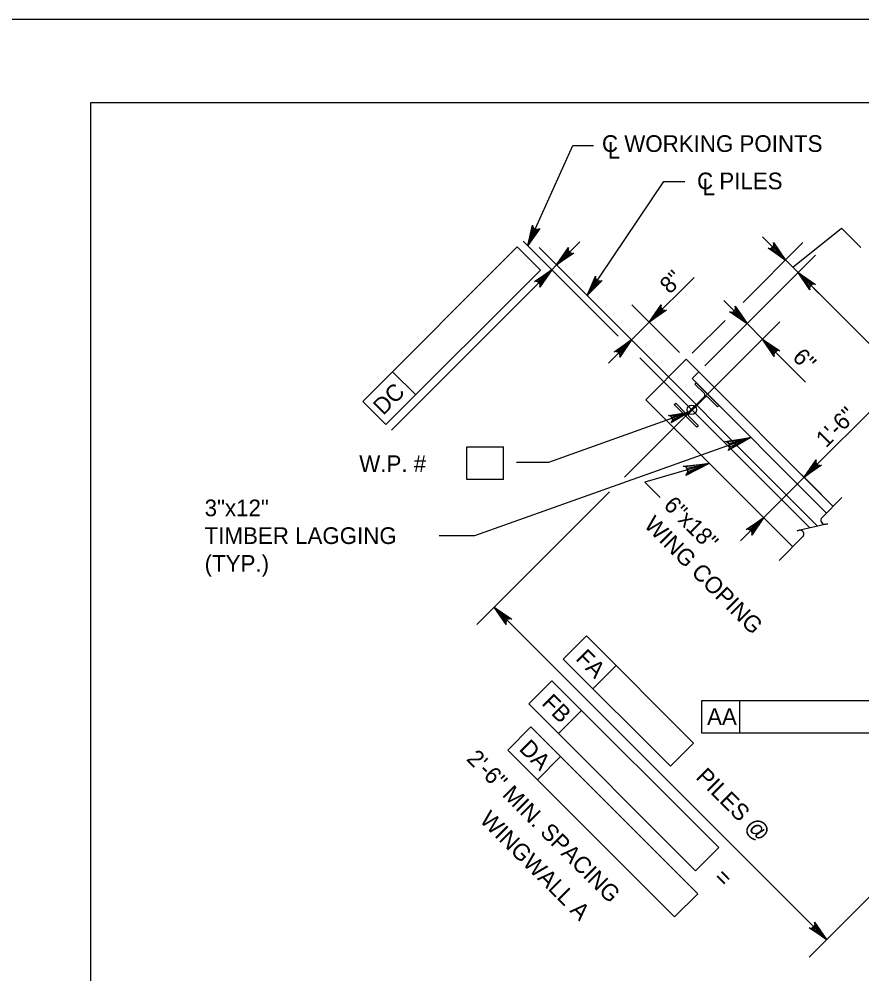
# Model space of a CAD drawing. Extents: x 638304 to 640306, y 296653 to 298435.
# Drawn here: x 639303.6 to 639455.2, y 298263.7 to 298435.5 of the extents above; entities that cross this region are included whole.
import ezdxf

# ---------------------------------------------------------------- set-up
doc = ezdxf.new("R2010")
doc.units = 0
for name, color, linetype in [('2', 7, 'Continuous'), ('3', 7, 'Continuous'), ('Level 2', 7, 'Continuous'), ('Level 3', 7, 'Continuous'), ('Level 4', 7, 'Continuous'), ('Level 5', 7, 'Continuous'), ('Level 52', 7, 'Continuous'), ('Level 8', 7, 'Continuous'), ('PLT-BNDY', 7, 'Continuous')]:
    doc.layers.add(name, color=color, linetype=linetype)

# ---------------------------------------------------------------- blocks, each defined once
blk = doc.blocks.new('HPILE')
at = {"layer": '3'}
for p, q in [((-0.12, -2.66), (-0.12, 2.66)), ((0.12, 2.66), (0.12, -2.66)), ((-3.67, -3.1), (-0.56, -3.1))]:
    blk.add_line(p, q, dxfattribs=at)
for points in [[(-0.56, 3.1), (-3.67, 3.1), (-3.67, 3.54), (3.67, 3.54), (3.67, 3.1), (0.56, 3.1)], [(0.56, -3.1), (3.67, -3.1), (3.67, -3.54), (-3.67, -3.54), (-3.67, -3.1)]]:
    blk.add_lwpolyline(points, dxfattribs=at)
for centre, start, end in [((-0.56, 2.66), 0, 90), ((0.56, 2.66), 90, 180), ((-0.56, -2.66), 270, 0), ((0.56, -2.66), 180, 270)]:
    blk.add_arc(centre, 0.438, start, end, dxfattribs=at)

msp = doc.modelspace()

# ---------------------------------------------------------------- linework, layer by layer
at = {"layer": '2'}
for p, q in [((639316.46, 297856.46), (639316.46, 298420.46)), ((639316.46, 298420.46), (640102.46, 298420.46))]:
    msp.add_line(p, q, dxfattribs=at)
at = {"layer": 'Level 2'}
for p, q in [((639423.59, 298374.28), (639416.29, 298366.99)), ((639450.03, 298347.83), (639423.59, 298374.28)), ((639442.74, 298340.54), (639416.29, 298366.99))]:
    msp.add_line(p, q, dxfattribs=at)
at = {"layer": 'Level 3'}
for p in [(639425.85, 298372.02), (639448.82, 298346.62)]:
    msp.add_line(p, (639424.63, 298370.81), dxfattribs=at)
at = {"layer": 'Level 4'}
for p, q in [((639403.15, 298412.72), (639406.91, 298412.72)), ((639419.56, 298406.24), (639423.31, 298406.24)), ((639442.75, 298390.82), (639451.5, 298397.87)), ((639451.5, 298397.87), (639455, 298394.38)), ((639443.7, 298389.87), (639437.27, 298396.3)), ((639365.41, 298366.69), (639393.19, 298394.48)), ((639393.19, 298394.48), (639397.36, 298390.31)), ((639411.32, 298378.45), (639394.24, 298395.52)), ((639413.54, 298377.97), (639397.13, 298394.38)), ((639400.26, 298391.25), (639404.42, 298395.42)), ((639433.79, 298384.49), (639444.56, 298395.26)), ((639441.44, 298392.13), (639438.83, 298394.73)), ((639426.93, 298373.11), (639446.82, 298393)), ((639400.26, 298391.25), (639399.39, 298390.38)), ((639369.57, 298362.52), (639397.36, 298390.31)), ((639399.39, 298390.38), (639370.55, 298361.55)), ((639416.92, 298380.95), (639424.98, 298389)), ((639502.92, 298330.64), (639443.7, 298389.87)), ((639446.47, 298387.09), (639448.56, 298385.01)), ((639447.22, 298344.29), (639407.29, 298384.21)), ((639422.39, 298375.48), (639413.8, 298384.07)), ((639426.93, 298373.11), (639437.63, 298383.81)), ((639434.51, 298380.69), (639430.34, 298384.85)), ((639440.41, 298381.03), (639412.47, 298353.09)), ((639413.74, 298377.76), (639416.92, 298380.95)), ((639424.67, 298375.37), (639430.57, 298381.26)), ((639434.51, 298380.69), (639437.29, 298377.91)), ((639413.74, 298377.76), (639409.58, 298373.6)), ((639437.29, 298377.91), (639445.02, 298370.18)), ((639445.8, 298343.97), (639415.26, 298374.51)), ((639370.74, 298372.03), (639374.91, 298367.86)), ((639444.8, 298353.07), (639460.41, 298368.69)), ((639365.41, 298366.69), (639369.57, 298362.52)), ((639384.1, 298358.56), (639390.68, 298358.56)), ((639384.1, 298352.66), (639384.1, 298358.56)), ((639390.68, 298352.66), (639390.68, 298358.56)), ((639437.5, 298345.78), (639444.8, 298353.07)), ((639444.36, 298353.51), (639447.92, 298349.95)), ((639390.68, 298352.66), (639384.1, 298352.66)), ((639409.8, 298350.42), (639385.93, 298326.55)), ((639437.06, 298346.22), (639440.63, 298342.65)), ((639437.5, 298345.78), (639433.34, 298341.61)), ((639448.82, 298269.91), (639389.05, 298329.67)), ((639405.64, 298324.52), (639401.47, 298320.35)), ((639405.64, 298324.52), (639424.89, 298305.26)), ((639401.47, 298320.35), (639420.73, 298301.09)), ((639410.97, 298319.18), (639406.8, 298315.02)), ((639399.41, 298316.47), (639395.24, 298312.31)), ((639399.41, 298316.47), (639429.42, 298286.46)), ((639395.24, 298312.31), (639425.25, 298282.3)), ((639426.36, 298312.93), (639461.6, 298312.93)), ((639426.36, 298307.03), (639426.36, 298312.93)), ((639433.2, 298307.03), (639433.2, 298312.93)), ((639404.75, 298311.14), (639400.58, 298306.97)), ((639395.64, 298308.15), (639391.47, 298303.98)), ((639395.64, 298308.15), (639425.65, 298278.14)), ((639461.6, 298307.03), (639426.36, 298307.03)), ((639424.89, 298305.26), (639420.73, 298301.09)), ((639391.47, 298303.98), (639421.48, 298273.98)), ((639400.98, 298302.82), (639396.81, 298298.65)), ((639473.45, 298294.53), (639445.7, 298266.78)), ((639429.42, 298286.46), (639425.25, 298282.3)), ((639425.65, 298278.14), (639421.48, 298273.98))]:
    msp.add_line(p, q, dxfattribs=at)
for points in [[(639395.06, 298394.71), (639403.15, 298412.72)], [(639405.77, 298385.73), (639419.56, 298406.24)], [(639395.06, 298394.71), (639395.94, 298398.39), (639396.01, 298398.05), (639396.17, 298397.81), (639396.38, 298397.67), (639396.63, 298397.61), (639396.92, 298397.64), (639397.22, 298397.82), (639395.06, 298394.71), (639396.92, 298397.64), (639396.63, 298397.61), (639395.06, 298394.71), (639396.38, 298397.67), (639396.17, 298397.81), (639395.06, 298394.71), (639396.01, 298398.05)], [(639400.26, 298391.25), (639402.4, 298394.38), (639402.33, 298394.03), (639402.41, 298393.75), (639402.55, 298393.54), (639402.76, 298393.4), (639403.04, 298393.33), (639403.38, 298393.39), (639400.26, 298391.25), (639403.04, 298393.33), (639402.76, 298393.4), (639400.26, 298391.25), (639402.55, 298393.54), (639402.41, 298393.75), (639400.26, 298391.25), (639402.33, 298394.03)], [(639441.44, 298392.13), (639438.31, 298394.27), (639438.66, 298394.21), (639438.94, 298394.28), (639439.14, 298394.42), (639439.29, 298394.63), (639439.36, 298394.91), (639439.3, 298395.25), (639441.44, 298392.13), (639439.36, 298394.91), (639439.29, 298394.63), (639441.44, 298392.13), (639439.14, 298394.42), (639438.94, 298394.28), (639441.44, 298392.13), (639438.66, 298394.21)], [(639399.39, 298390.38), (639397.25, 298387.25), (639397.31, 298387.6), (639397.24, 298387.88), (639397.09, 298388.09), (639396.89, 298388.23), (639396.6, 298388.3), (639396.26, 298388.24), (639399.39, 298390.38), (639396.6, 298388.3), (639396.89, 298388.23), (639399.39, 298390.38), (639397.09, 298388.09), (639397.24, 298387.88), (639399.39, 298390.38), (639397.31, 298387.6)], [(639405.77, 298385.73), (639407.27, 298389.21), (639407.28, 298388.86), (639407.4, 298388.6), (639407.59, 298388.42), (639407.82, 298388.32), (639408.11, 298388.3), (639408.43, 298388.43), (639405.77, 298385.73), (639408.11, 298388.3), (639407.82, 298388.32), (639405.77, 298385.73), (639407.59, 298388.42), (639407.4, 298388.6), (639405.77, 298385.73), (639407.28, 298388.86)], [(639443.7, 298389.87), (639446.82, 298387.74), (639446.48, 298387.8), (639446.2, 298387.72), (639445.99, 298387.58), (639445.84, 298387.37), (639445.77, 298387.09), (639445.83, 298386.75), (639443.7, 298389.87), (639445.77, 298387.09), (639445.84, 298387.37), (639443.7, 298389.87), (639445.99, 298387.58), (639446.2, 298387.72), (639443.7, 298389.87), (639446.48, 298387.8)], [(639416.92, 298380.95), (639419.06, 298384.07), (639419, 298383.73), (639419.07, 298383.45), (639419.22, 298383.24), (639419.42, 298383.09), (639419.71, 298383.02), (639420.05, 298383.08), (639416.92, 298380.95), (639419.71, 298383.02), (639419.42, 298383.09), (639416.92, 298380.95), (639419.22, 298383.24), (639419.07, 298383.45), (639416.92, 298380.95), (639419, 298383.73)], [(639434.51, 298380.69), (639431.38, 298382.82), (639431.73, 298382.76), (639432.01, 298382.83), (639432.22, 298382.98), (639432.36, 298383.19), (639432.43, 298383.47), (639432.37, 298383.81), (639434.51, 298380.69), (639432.43, 298383.47), (639432.36, 298383.19), (639434.51, 298380.69), (639432.22, 298382.98), (639432.01, 298382.83), (639434.51, 298380.69), (639431.73, 298382.76)], [(639413.74, 298377.76), (639411.61, 298374.64), (639411.67, 298374.98), (639411.59, 298375.27), (639411.45, 298375.47), (639411.24, 298375.62), (639410.96, 298375.69), (639410.62, 298375.63), (639413.74, 298377.76), (639410.96, 298375.69), (639411.24, 298375.62), (639413.74, 298377.76), (639411.45, 298375.47), (639411.59, 298375.27), (639413.74, 298377.76), (639411.67, 298374.98)], [(639437.29, 298377.91), (639440.41, 298375.77), (639440.07, 298375.83), (639439.79, 298375.76), (639439.58, 298375.61), (639439.44, 298375.41), (639439.36, 298375.13), (639439.42, 298374.78), (639437.29, 298377.91), (639439.36, 298375.13), (639439.44, 298375.41), (639437.29, 298377.91), (639439.58, 298375.61), (639439.79, 298375.76), (639437.29, 298377.91), (639440.07, 298375.83)], [(639424.13, 298364.75), (639398.83, 298355.74), (639393.04, 298355.74)], [(639424.13, 298364.75), (639420.86, 298362.84), (639421.06, 298363.13), (639421.12, 298363.41), (639421.07, 298363.66), (639420.95, 298363.88), (639420.73, 298364.07), (639420.39, 298364.16), (639424.13, 298364.75), (639420.73, 298364.07), (639420.95, 298363.88), (639424.13, 298364.75), (639421.07, 298363.66), (639421.12, 298363.41), (639424.13, 298364.75), (639421.06, 298363.13)], [(639435.21, 298360.23), (639385.48, 298342.55), (639379.16, 298342.55)], [(639444.8, 298353.07), (639446.94, 298356.2), (639446.87, 298355.85), (639446.95, 298355.57), (639447.09, 298355.37), (639447.3, 298355.22), (639447.58, 298355.15), (639447.92, 298355.21), (639444.8, 298353.07), (639447.58, 298355.15), (639447.3, 298355.22), (639444.8, 298353.07), (639447.09, 298355.37), (639446.95, 298355.57), (639444.8, 298353.07), (639446.87, 298355.85)], [(639427.72, 298355.52), (639416.12, 298352.18), (639418.9, 298349.41)], [(639437.5, 298345.78), (639435.37, 298342.65), (639435.43, 298343), (639435.36, 298343.28), (639435.21, 298343.48), (639435, 298343.63), (639434.72, 298343.7), (639434.38, 298343.64), (639437.5, 298345.78), (639434.72, 298343.7), (639435, 298343.63), (639437.5, 298345.78), (639435.21, 298343.48), (639435.36, 298343.28), (639437.5, 298345.78), (639435.43, 298343)], [(639389.05, 298329.67), (639392.18, 298327.54), (639391.84, 298327.6), (639391.55, 298327.53), (639391.35, 298327.38), (639391.2, 298327.17), (639391.13, 298326.89), (639391.19, 298326.55), (639389.05, 298329.67), (639391.13, 298326.89), (639391.2, 298327.17), (639389.05, 298329.67), (639391.35, 298327.38), (639391.55, 298327.53), (639389.05, 298329.67), (639391.84, 298327.6)], [(639448.82, 298269.91), (639445.7, 298272.04), (639446.04, 298271.98), (639446.32, 298272.05), (639446.53, 298272.2), (639446.67, 298272.41), (639446.75, 298272.69), (639446.68, 298273.03), (639448.82, 298269.91), (639446.75, 298272.69), (639446.67, 298272.41), (639448.82, 298269.91), (639446.53, 298272.2), (639446.32, 298272.05), (639448.82, 298269.91), (639446.04, 298271.98)]]:
    msp.add_lwpolyline(points, dxfattribs=at)
for points in [[(639395.06, 298394.71), (639396.49, 298397.3), (639396.04, 298397.5)], [(639439.7, 298394.56), (639439.01, 298393.87), (639441.44, 298392.13)], [(639401.99, 298393.68), (639402.69, 298392.99), (639400.26, 298391.25)], [(639396.96, 298388.64), (639397.65, 298387.95), (639399.39, 298390.38)], [(639446.13, 298388.14), (639445.43, 298387.44), (639443.7, 298389.87)], [(639405.77, 298385.73), (639407.62, 298388.04), (639407.22, 298388.32)], [(639418.66, 298383.38), (639419.35, 298382.68), (639416.92, 298380.95)], [(639432.77, 298383.12), (639432.08, 298382.42), (639434.51, 298380.69)], [(639411.31, 298376.03), (639412.01, 298375.33), (639413.74, 298377.76)], [(639439.72, 298376.17), (639439.02, 298375.48), (639437.29, 298377.91)], [(639424.13, 298364.75), (639421.27, 298363.99), (639421.43, 298363.53)], [(639435.21, 298360.23), (639432.35, 298359.47), (639432.52, 298359.01)], [(639446.53, 298355.5), (639447.23, 298354.81), (639444.8, 298353.07)], [(639435.07, 298344.04), (639435.77, 298343.35), (639437.5, 298345.78)], [(639391.49, 298327.94), (639390.79, 298327.24), (639389.05, 298329.67)], [(639447.09, 298272.34), (639446.39, 298271.64), (639448.82, 298269.91)]]:
    msp.add_lwpolyline(points, close=True, dxfattribs=at)
msp.add_circle((639424.57, 298365.19), 0.849, dxfattribs=at)
at = {"layer": 'Level 52'}
for points in [[(639435.21, 298360.23), (639431.12, 298357.85), (639431.37, 298358.2), (639431.44, 298358.56), (639431.39, 298358.87), (639431.23, 298359.15), (639430.96, 298359.38), (639430.54, 298359.49), (639435.21, 298360.23), (639430.96, 298359.38), (639431.23, 298359.15), (639435.21, 298360.23), (639431.39, 298358.87), (639431.44, 298358.56), (639435.21, 298360.23), (639431.37, 298358.2)], [(639427.72, 298355.52), (639423.49, 298353.39), (639423.77, 298353.73), (639423.86, 298354.08), (639423.83, 298354.4), (639423.69, 298354.68), (639423.42, 298354.93), (639423.01, 298355.07), (639427.72, 298355.52), (639423.42, 298354.93), (639423.69, 298354.68), (639427.72, 298355.52), (639423.83, 298354.4), (639423.86, 298354.08), (639427.72, 298355.52), (639423.77, 298353.73)]]:
    msp.add_lwpolyline(points, dxfattribs=at)
at = {"layer": 'Level 8'}
for p, q in [((639451.59, 298349.39), (639448.01, 298345.81)), ((639444.58, 298342.38), (639440.27, 298338.07))]:
    msp.add_line(p, q, dxfattribs=at)
msp.add_lwpolyline([(639448.69, 298344.62), (639449.04, 298344.7), (639443.51, 298343.44), (639443.88, 298343.53)], dxfattribs=at)
for centre, start, end in [((639448.51, 298345.31), 135, 285), ((639444.04, 298342.84), 320.3286, 102.8672)]:
    msp.add_arc(centre, 0.709, start, end, dxfattribs=at)
at = {"layer": 'PLT-BNDY'}
msp.add_lwpolyline([(639276.46, 298435.46), (640117.46, 298435.46), (640117.46, 297841.46), (639276.46, 297841.46)], close=True, dxfattribs=at)

# ---------------------------------------------------------------- block references
at = {"layer": 'Level 3', "xscale": 0.7859001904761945, "yscale": 0.7859001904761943, "rotation": -45.00000000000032}
msp.add_blockref('HPILE', (639425.44, 298366.06), dxfattribs=at)

# ---------------------------------------------------------------- texts
at = {"layer": 'Level 4'}
for s, height, p in [('C WORKING POINTS', 3.0001, (639408.42, 298411.57)), ('L', 3, (639409.45, 298410.37)), ('C PILES', 3, (639425.52, 298404.85)), ('L', 3, (639426.51, 298403.78)), ('W.P. # ', 3, (639364.76, 298353.99)), ('AA', 3, (639427.33, 298308.52))]:
    msp.add_text(s, height=height, dxfattribs=at).set_placement(p)
for s, height, rotation, p in [('8"', 3, 45, (639420.63, 298385.87)), ('DC', 3, 45, (639369.07, 298364.06)), ('FA', 3, 314.9382, (639403.54, 298320.32)), ('FB', 3, 314.9382, (639397.41, 298312.27)), ('DA', 3, 314.9382, (639393.36, 298304.06)), ('2\'-6" MIN. SPACING', 3.0001, 315, (639383.9, 298302.26)), ('PILES @', 3, 314.9382, (639425.13, 298298.98)), ('WINGWALL A', 3, 315, (639386.26, 298291.24)), ('=', 3, 314.9382, (639428.37, 298280.87))]:
    msp.add_text(s, height=height, rotation=rotation, dxfattribs=at).set_placement(p)
at = {"layer": 'Level 5'}
for s, height, rotation, p in [('6"', 3, 315, (639442.51, 298374.45)), ('1\'-6"', 3, 45, (639448.72, 298358.22)), ('6"x18"', 3, 315, (639419.34, 298347.82)), ('WING COPING', 3.0001, 315, (639415.81, 298344.29))]:
    msp.add_text(s, height=height, rotation=rotation, dxfattribs=at).set_placement(p)
for s, height, p in [('3"x12"', 3, (639336.95, 298346.05)), ('TIMBER LAGGING', 3.0001, (639336.95, 298341.06)), ('(TYP.)', 3, (639336.95, 298336.06))]:
    msp.add_text(s, height=height, dxfattribs=at).set_placement(p)

doc.saveas('drawing.dxf')
